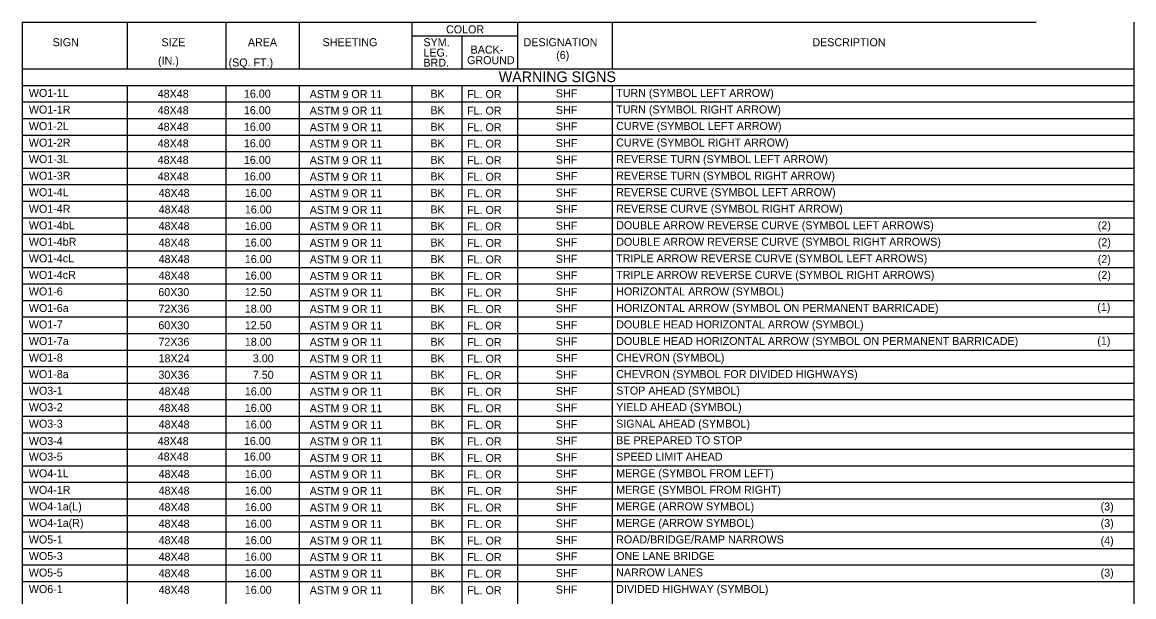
# Model space of a CAD drawing. Extents: x -439.1 to -408.3, y -458.1 to -437.7.
# Drawn here: x -439.11 to -419.21, y -447.95 to -437.68 of the extents above; entities that cross this region are included whole.
import ezdxf

# ---------------------------------------------------------------- set-up
doc = ezdxf.new("R2010")
doc.units = 0
doc.layers.add('Level 4', color=7, linetype='Continuous')
doc.layers.add('Level 45', color=7, linetype='Continuous')

msp = doc.modelspace()

# ---------------------------------------------------------------- linework, layer by layer
at = {"layer": 'Level 4'}
for p, q in [((-439.109, -437.676), (-420.961, -437.676)), ((-439.109, -437.676), (-439.109, -457.138)), ((-437.233, -437.676), (-437.233, -438.508)), ((-435.462, -437.676), (-435.462, -438.508)), ((-434.152, -437.676), (-434.152, -438.508)), ((-432.136, -437.676), (-432.136, -438.508)), ((-430.244, -437.676), (-430.244, -438.508)), ((-428.547, -437.676), (-428.547, -438.508)), ((-419.212, -437.676), (-419.212, -458.051)), ((-432.136, -437.921), (-430.244, -437.921)), ((-431.24, -437.921), (-431.24, -438.508)), ((-439.109, -438.508), (-419.212, -438.508)), ((-439.109, -438.806), (-419.212, -438.806)), ((-437.233, -438.806), (-437.233, -458.051)), ((-435.462, -438.806), (-435.462, -458.051)), ((-434.152, -438.806), (-434.152, -458.051)), ((-432.136, -438.806), (-432.136, -458.051)), ((-431.24, -438.806), (-431.24, -458.051)), ((-430.244, -438.806), (-430.244, -458.051)), ((-428.547, -438.806), (-428.547, -458.051)), ((-439.109, -439.102), (-419.212, -439.102)), ((-439.109, -439.398), (-419.212, -439.398)), ((-439.109, -439.693), (-419.212, -439.693)), ((-439.109, -439.989), (-419.212, -439.989)), ((-439.109, -440.285), (-419.212, -440.285)), ((-439.109, -440.581), (-419.212, -440.581)), ((-439.109, -440.877), (-419.212, -440.877)), ((-439.109, -441.173), (-419.212, -441.173)), ((-439.109, -441.468), (-419.212, -441.468)), ((-439.109, -441.764), (-419.212, -441.764)), ((-439.109, -442.06), (-419.212, -442.06)), ((-439.109, -442.356), (-419.212, -442.356)), ((-439.109, -442.652), (-419.212, -442.652)), ((-439.109, -442.947), (-419.212, -442.947)), ((-439.109, -443.243), (-419.212, -443.243)), ((-439.109, -443.539), (-419.212, -443.539)), ((-439.109, -443.835), (-419.212, -443.835)), ((-439.109, -444.131), (-419.212, -444.131)), ((-439.109, -444.426), (-419.212, -444.426)), ((-439.109, -444.722), (-419.212, -444.722)), ((-439.109, -445.018), (-419.212, -445.018)), ((-439.109, -445.314), (-419.212, -445.314)), ((-439.109, -445.61), (-419.212, -445.61)), ((-439.109, -445.905), (-419.212, -445.905)), ((-439.109, -446.201), (-419.212, -446.201)), ((-439.109, -446.497), (-419.212, -446.497)), ((-439.109, -446.793), (-419.212, -446.793)), ((-439.109, -447.089), (-419.212, -447.089)), ((-439.109, -447.384), (-419.212, -447.384)), ((-439.109, -447.68), (-419.212, -447.68))]:
    msp.add_line(p, q, dxfattribs=at)

# ---------------------------------------------------------------- texts
for s, height, p in [('COLOR', 0.1431, (-431.522, -437.875)), ('SIGN', 0.1433, (-438.565, -438.105)), ('SIZE', 0.1433, (-436.616, -438.105)), ('AREA', 0.1433, (-435.07, -438.105)), ('SHEETING', 0.1433, (-433.732, -438.105)), ('SYM.', 0.1433, (-431.927, -438.104)), ('BACK-', 0.1433, (-431.083, -438.237)), ('DESIGNATION', 0.14328, (-430.134, -438.105)), ('DESCRIPTION', 0.14328, (-424.965, -438.105)), ('LEG.', 0.1433, (-431.927, -438.29)), ('BRD.', 0.1433, (-431.927, -438.47)), ('GROUND', 0.1433, (-431.146, -438.426)), ('(6)', 0.1433, (-429.551, -438.333)), ('WARNING SIGNS', 0.19076, (-430.579, -438.747)), ('WO1-1L', 0.1433, (-438.991, -439.013)), ('ASTM 9 OR 11', 0.14328, (-433.962, -439.033)), ('BK', 0.1433, (-431.802, -439.026)), ('FL. OR', 0.1433, (-431.146, -439.033)), ('SHF', 0.1433, (-429.557, -439.02)), ('TURN (SYMBOL LEFT ARROW) ', 0.14328, (-428.477, -439.012)), ('WO1-1R', 0.1433, (-438.991, -439.309)), ('ASTM 9 OR 11', 0.14328, (-433.962, -439.329)), ('BK', 0.1433, (-431.802, -439.321)), ('FL. OR', 0.1433, (-431.146, -439.329)), ('SHF', 0.1433, (-429.557, -439.316)), ('TURN (SYMBOL RIGHT ARROW)', 0.14328, (-428.477, -439.308)), ('WO1-2L', 0.1433, (-438.991, -439.605)), ('ASTM 9 OR 11', 0.14328, (-433.962, -439.625)), ('BK', 0.1433, (-431.802, -439.617)), ('FL. OR', 0.1433, (-431.146, -439.625)), ('SHF', 0.1433, (-429.557, -439.612)), ('CURVE (SYMBOL LEFT ARROW) ', 0.14328, (-428.477, -439.603)), ('WO1-2R', 0.1433, (-438.991, -439.901)), ('ASTM 9 OR 11', 0.14328, (-433.962, -439.92)), ('BK', 0.1433, (-431.802, -439.913)), ('FL. OR', 0.1433, (-431.146, -439.92)), ('SHF', 0.1433, (-429.557, -439.908)), ('CURVE (SYMBOL RIGHT ARROW) ', 0.14328, (-428.477, -439.899)), ('WO1-3L', 0.1433, (-438.991, -440.196)), ('ASTM 9 OR 11', 0.14328, (-433.962, -440.216)), ('BK', 0.1433, (-431.802, -440.209)), ('FL. OR', 0.1433, (-431.146, -440.216)), ('SHF', 0.1433, (-429.557, -440.204)), ('REVERSE TURN (SYMBOL LEFT ARROW) ', 0.14328, (-428.477, -440.195)), ('WO1-3R', 0.1433, (-438.991, -440.492)), ('ASTM 9 OR 11', 0.14328, (-433.962, -440.512)), ('BK', 0.1433, (-431.802, -440.505)), ('FL. OR', 0.1433, (-431.146, -440.512)), ('SHF', 0.1433, (-429.557, -440.499)), ('REVERSE TURN (SYMBOL RIGHT ARROW) ', 0.14328, (-428.477, -440.491)), ('WO1-4L', 0.1433, (-438.991, -440.788)), ('ASTM 9 OR 11', 0.14328, (-433.962, -440.808)), ('BK', 0.1433, (-431.802, -440.8)), ('FL. OR', 0.1433, (-431.146, -440.808)), ('SHF', 0.1433, (-429.557, -440.795)), ('REVERSE CURVE (SYMBOL LEFT ARROW) ', 0.14328, (-428.477, -440.787)), ('WO1-4R', 0.1433, (-438.991, -441.084)), ('ASTM 9 OR 11', 0.14328, (-433.962, -441.104)), ('BK', 0.1433, (-431.802, -441.096)), ('FL. OR', 0.1433, (-431.146, -441.104)), ('SHF', 0.1433, (-429.557, -441.091)), ('REVERSE CURVE (SYMBOL RIGHT ARROW) ', 0.14328, (-428.477, -441.083)), ('WO1-4bL', 0.1433, (-438.991, -441.38)), ('ASTM 9 OR 11', 0.14328, (-433.962, -441.399)), ('BK', 0.1433, (-431.802, -441.392)), ('FL. OR', 0.1433, (-431.146, -441.4)), ('SHF', 0.1433, (-429.557, -441.387)), ('DOUBLE ARROW REVERSE CURVE (SYMBOL LEFT ARROWS) ', 0.14328, (-428.477, -441.378)), ('(2)', 0.1433, (-419.856, -441.38)), ('WO1-4bR', 0.1433, (-438.991, -441.675)), ('ASTM 9 OR 11', 0.14328, (-433.962, -441.695)), ('BK', 0.1433, (-431.802, -441.688)), ('FL. OR', 0.1433, (-431.146, -441.695)), ('SHF', 0.1433, (-429.557, -441.683)), ('DOUBLE ARROW REVERSE CURVE (SYMBOL RIGHT ARROWS) ', 0.14328, (-428.477, -441.674)), ('(2)', 0.1433, (-419.856, -441.682)), ('WO1-4cL', 0.1433, (-438.991, -441.971)), ('ASTM 9 OR 11', 0.14328, (-433.962, -441.991)), ('BK', 0.1433, (-431.802, -441.984)), ('FL. OR', 0.1433, (-431.146, -441.991)), ('SHF', 0.1433, (-429.557, -441.979)), ('TRIPLE ARROW REVERSE CURVE (SYMBOL LEFT ARROWS) ', 0.14328, (-428.477, -441.97)), ('(2)', 0.1433, (-419.856, -441.985)), ('WO1-4cR', 0.1433, (-438.991, -442.267)), ('ASTM 9 OR 11', 0.14328, (-433.962, -442.287)), ('BK', 0.1433, (-431.802, -442.279)), ('FL. OR', 0.1433, (-431.146, -442.287)), ('SHF', 0.1433, (-429.557, -442.274)), ('TRIPLE ARROW REVERSE CURVE (SYMBOL RIGHT ARROWS) ', 0.14328, (-428.477, -442.266)), ('(2)', 0.1433, (-419.856, -442.268)), ('WO1-6', 0.1433, (-438.991, -442.563)), ('ASTM 9 OR 11', 0.14328, (-433.962, -442.583)), ('BK', 0.1433, (-431.802, -442.575)), ('FL. OR', 0.1433, (-431.146, -442.583)), ('SHF', 0.1433, (-429.557, -442.57)), ('HORIZONTAL ARROW (SYMBOL)', 0.14328, (-428.477, -442.562)), ('(1)', 0.1433, (-419.865, -442.84)), ('WO1-6a', 0.1433, (-438.991, -442.859)), ('ASTM 9 OR 11', 0.14328, (-433.962, -442.878)), ('BK', 0.1433, (-431.802, -442.871)), ('FL. OR', 0.1433, (-431.146, -442.879)), ('SHF', 0.1433, (-429.557, -442.866)), ('HORIZONTAL ARROW (SYMBOL ON PERMANENT BARRICADE)', 0.14328, (-428.477, -442.857)), ('WO1-7', 0.1433, (-438.991, -443.154)), ('ASTM 9 OR 11', 0.14328, (-433.962, -443.174)), ('BK', 0.1433, (-431.802, -443.167)), ('FL. OR', 0.1433, (-431.146, -443.174)), ('SHF', 0.1433, (-429.557, -443.162)), ('DOUBLE HEAD HORIZONTAL ARROW (SYMBOL)', 0.14328, (-428.477, -443.153)), ('DOUBLE HEAD HORIZONTAL ARROW (SYMBOL ON PERMANENT BARRICADE)', 0.14328, (-428.477, -443.449)), ('(1)', 0.1433, (-419.865, -443.444)), ('WO1-7a', 0.1433, (-438.991, -443.45)), ('ASTM 9 OR 11', 0.14328, (-433.962, -443.47)), ('BK', 0.1433, (-431.802, -443.463)), ('FL. OR', 0.1433, (-431.146, -443.47)), ('SHF', 0.1433, (-429.557, -443.458)), ('WO1-8', 0.1433, (-438.991, -443.746)), ('ASTM 9 OR 11', 0.14328, (-433.962, -443.766)), ('BK', 0.1433, (-431.802, -443.759)), ('FL. OR', 0.1433, (-431.146, -443.766)), ('SHF', 0.1433, (-429.557, -443.753)), ('CHEVRON (SYMBOL)', 0.14328, (-428.477, -443.745)), ('WO1-8a', 0.1433, (-438.991, -444.042)), ('CHEVRON (SYMBOL FOR DIVIDED HIGHWAYS)', 0.14328, (-428.477, -444.041)), ('ASTM 9 OR 11', 0.14328, (-433.962, -444.062)), ('BK', 0.1433, (-431.802, -444.054)), ('FL. OR', 0.1433, (-431.146, -444.062)), ('SHF', 0.1433, (-429.557, -444.049)), ('WO3-1', 0.1433, (-438.991, -444.338)), ('ASTM 9 OR 11', 0.14328, (-433.962, -444.357)), ('BK', 0.1433, (-431.802, -444.35)), ('FL. OR', 0.1433, (-431.146, -444.358)), ('SHF', 0.1433, (-429.557, -444.345)), ('STOP AHEAD (SYMBOL) ', 0.14328, (-428.477, -444.336)), ('WO3-2', 0.1433, (-438.991, -444.633)), ('SHF', 0.1433, (-429.557, -444.641)), ('YIELD AHEAD (SYMBOL) ', 0.14328, (-428.477, -444.632)), ('ASTM 9 OR 11', 0.14328, (-433.962, -444.653)), ('BK', 0.1433, (-431.802, -444.646)), ('FL. OR', 0.1433, (-431.146, -444.653)), ('WO3-3 ', 0.1433, (-438.991, -444.929)), ('ASTM 9 OR 11', 0.14328, (-433.962, -444.949)), ('BK', 0.1433, (-431.802, -444.942)), ('FL. OR', 0.1433, (-431.146, -444.949)), ('SHF', 0.1433, (-429.557, -444.937)), ('SIGNAL AHEAD (SYMBOL)', 0.14328, (-428.477, -444.928)), ('WO3-4', 0.1433, (-438.991, -445.238)), ('SHF', 0.1433, (-429.557, -445.232)), ('BE PREPARED TO STOP ', 0.14328, (-428.477, -445.224)), ('ASTM 9 OR 11', 0.14328, (-433.962, -445.245)), ('BK', 0.1433, (-431.802, -445.238)), ('FL. OR', 0.1433, (-431.146, -445.245)), ('WO3-5', 0.1433, (-438.991, -445.517)), ('ASTM 9 OR 11', 0.14328, (-433.962, -445.541)), ('BK', 0.1433, (-431.802, -445.516)), ('FL. OR', 0.1433, (-431.146, -445.541)), ('SHF', 0.1433, (-429.557, -445.528)), ('SPEED LIMIT AHEAD ', 0.14328, (-428.477, -445.519)), ('WO4-1L ', 0.1433, (-438.991, -445.817)), ('BK', 0.1433, (-431.802, -445.829)), ('SHF', 0.1433, (-429.557, -445.824)), ('MERGE (SYMBOL FROM LEFT)', 0.14328, (-428.477, -445.815)), ('ASTM 9 OR 11', 0.14328, (-433.962, -445.837)), ('FL. OR', 0.1433, (-431.146, -445.837)), ('WO4-1R ', 0.1433, (-438.991, -446.112)), ('ASTM 9 OR 11', 0.14328, (-433.962, -446.132)), ('BK', 0.1433, (-431.802, -446.125)), ('FL. OR', 0.1433, (-431.146, -446.132)), ('SHF', 0.1433, (-429.557, -446.12)), ('MERGE (SYMBOL FROM RIGHT)', 0.14328, (-428.477, -446.111)), ('WO4-1a(L)', 0.1433, (-438.991, -446.408)), ('ASTM 9 OR 11', 0.14328, (-433.962, -446.428)), ('BK', 0.1433, (-431.802, -446.421)), ('FL. OR', 0.1433, (-431.146, -446.428)), ('SHF', 0.1433, (-429.557, -446.416)), ('MERGE (ARROW SYMBOL)', 0.14328, (-428.477, -446.407)), ('(3)', 0.1433, (-419.806, -446.41)), ('WO4-1a(R)', 0.1433, (-438.991, -446.704)), ('ASTM 9 OR 11', 0.14328, (-433.962, -446.724)), ('BK', 0.1433, (-431.802, -446.717)), ('FL. OR', 0.1433, (-431.146, -446.724)), ('SHF', 0.1433, (-429.557, -446.711)), ('MERGE (ARROW SYMBOL)', 0.14328, (-428.477, -446.703)), ('(3)', 0.1433, (-419.806, -446.706)), ('WO5-1 ', 0.1433, (-438.991, -447)), ('ASTM 9 OR 11', 0.14328, (-433.962, -447.02)), ('BK', 0.1433, (-431.802, -447.012)), ('FL. OR', 0.1433, (-431.146, -447.02)), ('SHF', 0.1433, (-429.557, -447.007)), ('ROAD/BRIDGE/RAMP NARROWS ', 0.14328, (-428.477, -446.999)), ('(4)', 0.1433, (-419.806, -447.018)), ('WO5-3 ', 0.1433, (-438.991, -447.296)), ('ASTM 9 OR 11', 0.14328, (-433.962, -447.316)), ('BK', 0.1433, (-431.802, -447.308)), ('FL. OR', 0.1433, (-431.146, -447.316)), ('SHF', 0.1433, (-429.557, -447.303)), ('ONE LANE BRIDGE', 0.14328, (-428.477, -447.294)), ('WO5-5', 0.1433, (-438.991, -447.592)), ('ASTM 9 OR 11', 0.14328, (-433.962, -447.611)), ('BK', 0.1433, (-431.802, -447.604)), ('FL. OR', 0.1433, (-431.146, -447.611)), ('SHF', 0.1433, (-429.557, -447.599)), ('NARROW LANES ', 0.14328, (-428.477, -447.59)), ('(3)', 0.1433, (-419.806, -447.593)), ('WO6-1 ', 0.1433, (-438.991, -447.887)), ('ASTM 9 OR 11', 0.14328, (-433.962, -447.907)), ('BK', 0.1433, (-431.802, -447.9)), ('FL. OR', 0.1433, (-431.146, -447.907)), ('SHF', 0.1433, (-429.557, -447.895)), ('DIVIDED HIGHWAY (SYMBOL)', 0.14328, (-428.477, -447.886))]:
    msp.add_text(s, height=height, dxfattribs=at).set_placement(p)
at = {"layer": 'Level 45'}
for s, p in [('(IN.)', (-436.678, -438.436)), ('(SQ. FT.)', (-435.416, -438.467)), ('48X48', (-436.684, -439.026)), ('16.00', (-435.141, -439.026)), ('48X48', (-436.684, -439.321)), ('16.00', (-435.141, -439.321)), ('48X48', (-436.684, -439.617)), ('16.00', (-435.141, -439.617)), ('48X48', (-436.684, -439.913)), ('16.00', (-435.141, -439.913)), ('48X48', (-436.684, -440.209)), ('16.00', (-435.141, -440.209)), ('48X48', (-436.684, -440.505)), ('16.00', (-435.141, -440.505)), ('48X48', (-436.668, -440.8)), ('16.00', (-435.124, -440.8)), ('48X48', (-436.668, -441.096)), ('16.00', (-435.124, -441.096)), ('48X48', (-436.668, -441.392)), ('16.00', (-435.124, -441.392)), ('48X48', (-436.668, -441.688)), ('16.00', (-435.124, -441.688)), ('48X48', (-436.668, -441.984)), ('16.00', (-435.124, -441.984)), ('48X48', (-436.668, -442.279)), ('16.00', (-435.124, -442.279)), ('60X30', (-436.673, -442.575)), ('12.50', (-435.124, -442.575)), ('72X36', (-436.671, -442.871)), ('18.00', (-435.124, -442.871)), ('60X30', (-436.673, -443.167)), ('12.50', (-435.124, -443.167)), ('72X36', (-436.671, -443.463)), ('18.00', (-435.124, -443.463)), ('18X24', (-436.668, -443.759)), ('3.00', (-434.981, -443.759)), ('30X36', (-436.671, -444.054)), ('7.50', (-434.981, -444.054)), ('48X48', (-436.668, -444.35)), ('16.00', (-435.124, -444.35)), ('48X48', (-436.668, -444.646)), ('16.00', (-435.124, -444.646)), ('48X48', (-436.668, -444.942)), ('16.00', (-435.124, -444.942)), ('48X48', (-436.684, -445.238)), ('16.00', (-435.141, -445.238)), ('48X48', (-436.684, -445.516)), ('16.00', (-435.141, -445.516)), ('48X48', (-436.668, -445.829)), ('16.00', (-435.124, -445.829)), ('48X48', (-436.668, -446.125)), ('16.00', (-435.124, -446.125)), ('48X48', (-436.668, -446.421)), ('16.00', (-435.124, -446.421)), ('48X48', (-436.668, -446.717)), ('16.00', (-435.124, -446.717)), ('48X48', (-436.668, -447.012)), ('16.00', (-435.124, -447.012)), ('48X48', (-436.668, -447.308)), ('16.00', (-435.124, -447.308)), ('48X48', (-436.668, -447.604)), ('16.00', (-435.124, -447.604)), ('48X48', (-436.668, -447.9)), ('16.00', (-435.124, -447.9))]:
    msp.add_text(s, height=0.1433, dxfattribs=at).set_placement(p)

doc.saveas('drawing.dxf')
